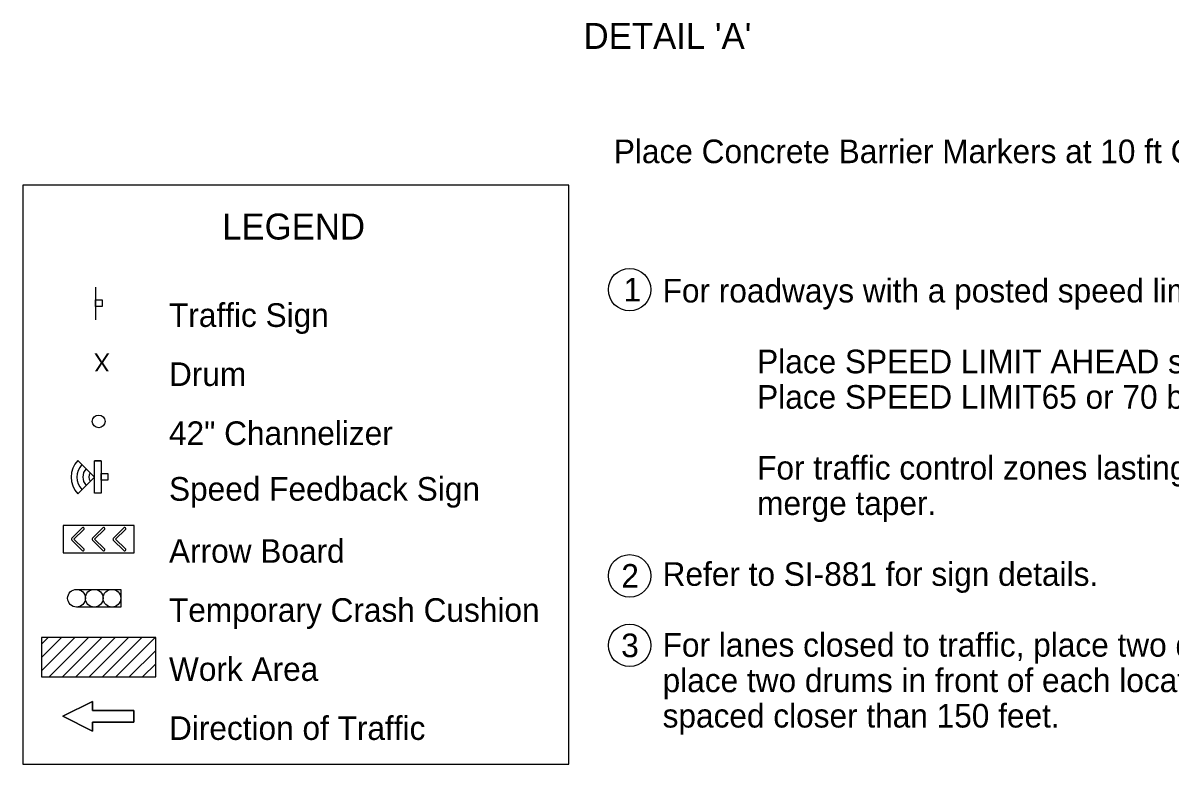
# Model space of a CAD drawing. Extents: x 10133 to 2270741, y 5363 to 1733450.
# Drawn here: x 24597 to 25567, y 5397 to 6025 of the extents above; entities that cross this region are included whole.
import ezdxf

# ---------------------------------------------------------------- set-up
doc = ezdxf.new("R2010")
doc.units = 0
for name, color, linetype in [('dsnNonPlotable', 7, 'Continuous'), ('dsnShtPlotShapeBatchPrint', 7, 'Continuous'), ('dsnstdblockInterim', 7, 'Continuous'), ('dsnStdBlockModified', 7, 'Continuous'), ('dsnStdBorder', 7, 'Continuous'), ('dsnStdTable', 7, 'Continuous')]:
    doc.layers.add(name, color=color, linetype=linetype)

msp = doc.modelspace()

# ---------------------------------------------------------------- linework, layer by layer
at = {"layer": 'dsnNonPlotable'}
msp.add_lwpolyline([(24596.56, 5887.64), (24596.56, 5397.41), (25058.44, 5397.41), (25058.44, 5887.64), (24596.56, 5887.64)], dxfattribs=at)
at = {"layer": 'dsnShtPlotShapeBatchPrint'}
for centre in [(25110.01, 5799.19), (25110.01, 5556.79), (25110.01, 5497.95)]:
    msp.add_circle(centre, 18, dxfattribs=at)
at = {"layer": 'dsnStdBlockModified'}
for p, q in [((24642.96, 5654.6), (24657.1, 5640.46)), ((24662.73, 5654.21), (24657.1, 5654.21)), ((24657.1, 5640.46), (24642.96, 5626.32)), ((24662.73, 5626.71), (24657.1, 5626.71))]:
    msp.add_line(p, q, dxfattribs=at)
for radius, start, end in [(20.32, 135.88004, 224.03126), (15.33, 136.16647, 223.71595), (10.34, 136.72938, 223.09626), (5.32, 138.70055, 221.29945)]:
    msp.add_arc((24657.57, 5640.44), radius, start, end, dxfattribs=at)
at = {"layer": 'dsnStdBorder'}
for p, q in [((24658, 5801.27), (24658, 5773.77)), ((24662.73, 5654.21), (24662.73, 5626.71)), ((24637.87, 5588.61), (24646.68, 5597.42)), ((24655.41, 5588.61), (24664.22, 5597.42)), ((24673.06, 5588.61), (24681.87, 5597.42)), ((24641.9, 5545.37), (24679.41, 5545.37)), ((24679.41, 5545.37), (24679.41, 5530.37)), ((24679.41, 5530.37), (24641.9, 5530.37)), ((24612.33, 5498.87), (24617.98, 5504.51)), ((24612.33, 5487.56), (24629.29, 5504.51)), ((24612.33, 5476.24), (24640.6, 5504.51)), ((24618.63, 5471.23), (24651.92, 5504.51)), ((24629.95, 5471.23), (24663.23, 5504.51)), ((24641.26, 5471.23), (24674.55, 5504.51)), ((24652.57, 5471.23), (24685.86, 5504.51)), ((24663.89, 5471.23), (24697.17, 5504.51)), ((24675.2, 5471.23), (24708.49, 5504.51)), ((24686.52, 5471.23), (24708.97, 5493.68)), ((24697.83, 5471.23), (24708.97, 5482.37))]:
    msp.add_line(p, q, dxfattribs=at)
for points in [[(24658.1, 5784.82), (24658.1, 5790.45), (24663.72, 5790.45), (24663.72, 5784.82)], [(24657.1, 5626.71), (24657.1, 5654.21), (24662.73, 5654.21), (24662.73, 5626.71)], [(24662.73, 5637.76), (24662.73, 5643.39), (24668.35, 5643.39), (24668.35, 5637.76)], [(24690.65, 5599.34), (24630.65, 5599.34), (24630.65, 5576.4), (24690.65, 5576.4)], [(24612.33, 5504.51), (24612.33, 5471.23), (24708.97, 5471.23), (24708.97, 5504.51)], [(24690.34, 5442.87), (24690.34, 5432.87), (24655.34, 5432.87), (24655.34, 5425.37), (24630.34, 5437.87), (24655.34, 5450.37), (24655.34, 5442.87)]]:
    msp.add_lwpolyline(points, close=True, dxfattribs=at)
for points in [[(24648.14, 5595.97), (24648.1, 5595.93), (24639.62, 5587.87), (24648.11, 5579.8)], [(24665.68, 5595.97), (24665.64, 5595.93), (24657.16, 5587.87), (24665.65, 5579.8)], [(24683.33, 5595.97), (24683.29, 5595.93), (24674.81, 5587.87), (24683.3, 5579.8)], [(24646.7, 5578.3), (24646.67, 5578.33), (24637.87, 5587.14), (24637.86, 5587.15)], [(24664.24, 5578.3), (24664.21, 5578.33), (24655.41, 5587.14), (24655.4, 5587.15)], [(24681.89, 5578.3), (24681.86, 5578.33), (24673.05, 5587.14), (24673.04, 5587.15)], [(24655.34, 5442.87), (24655.34, 5450.37), (24630.34, 5437.87), (24655.34, 5425.37), (24655.34, 5432.87), (24690.34, 5432.87), (24690.34, 5442.87), (24655.34, 5442.87)]]:
    msp.add_lwpolyline(points, dxfattribs=at)
for centre, radius in [((24660.65, 5687.64), 5.37), ((24660.65, 5687.64), 5.37), ((24641.9, 5537.87), 7.5), ((24641.9, 5537.87), 7.5), ((24656.9, 5537.87), 7.5), ((24656.9, 5537.87), 7.5), ((24671.9, 5537.87), 7.5), ((24671.91, 5537.87), 7.5)]:
    msp.add_circle(centre, radius, dxfattribs=at)
for centre, start, end in [((24647.41, 5596.69), 315.09746, 135.28103), ((24664.95, 5596.69), 315.09746, 135.28103), ((24682.6, 5596.69), 315.09746, 135.28103), ((24638.59, 5587.87), 134.16156, 224.60983), ((24656.13, 5587.87), 134.16156, 224.60983), ((24673.78, 5587.87), 134.16156, 224.60983), ((24647.41, 5579.05), 226.201, 47.36018), ((24664.95, 5579.05), 226.201, 47.36018), ((24682.6, 5579.05), 226.201, 47.36018)]:
    msp.add_arc(centre, 1.03, start, end, dxfattribs=at)

# ---------------------------------------------------------------- texts
at = {"layer": 'dsnShtPlotShapeBatchPrint'}
for s, p in [('1', (25104.81, 5789.19)), ('2', (25102.98, 5546.79)), ('3', (25102.87, 5487.95))]:
    msp.add_text(s, height=20, dxfattribs=at).set_placement(p)
at = {"layer": 'dsnstdblockInterim'}
msp.add_text("DETAIL 'A'", height=22, dxfattribs=at).set_placement((25071.02, 6003.07))
at = {"layer": 'dsnStdBorder'}
for s, height, p in [('LEGEND', 22, (24765.11, 5841.64)), ('Traffic Sign', 20, (24720.17, 5767.64)), ('Drum', 20, (24720.17, 5717.64)), ('42" Channelizer ', 20, (24720.17, 5667.64)), ('Speed Feedback Sign', 20, (24720.17, 5620.46)), ('Arrow Board', 20, (24720.17, 5567.87)), ('Temporary Crash Cushion', 20, (24720.17, 5517.87)), ('Work Area', 20, (24720.17, 5467.87)), ('Direction of Traffic', 20, (24720.17, 5417.87))]:
    msp.add_text(s, height=height, dxfattribs=at).set_placement(p)
msp.add_text('X', height=15, rotation=180, dxfattribs=at).set_placement((24670.08, 5745.14))
at = {"layer": 'dsnStdTable'}
for s, height, p in [('Place Concrete Barrier Markers at 10 ft C/C on bridge rail.', 20, (25096.66, 5906.3)), ('For roadways with a posted speed limit of 60 mph or greater before road work:', 20, (25137.94, 5788.35)), ('Place SPEED LIMIT AHEAD sign and SPEED LIMIT 55 sign prior to the lane closure as shown. ', 20, (25217.94, 5728.35)), ('Place SPEED LIMIT65 or 70 beyond the work area as shown.', 20, (25217.94, 5698.35)), ('For traffic control zones lasting more than 4 hours, place a Speed Feedback Sign at the end of the ', 20, (25217.94, 5638.35)), ('merge taper.', 20, (25217.94, 5608.35)), ('Refer to SI-881 for sign details.', 20, (25137.94, 5548.35)), ('For lanes closed to traffic, place two drums every 1000 feet. For full depth excavations in a closed lane, ', 20.00004, (25137.94, 5488.35)), ('place two drums in front of each location. Additional drums need not be placed for full depth excavations ', 20.00004, (25137.94, 5458.35)), ('spaced closer than 150 feet.', 20, (25137.94, 5428.35))]:
    msp.add_text(s, height=height, dxfattribs=at).set_placement(p)

doc.saveas('drawing.dxf')
